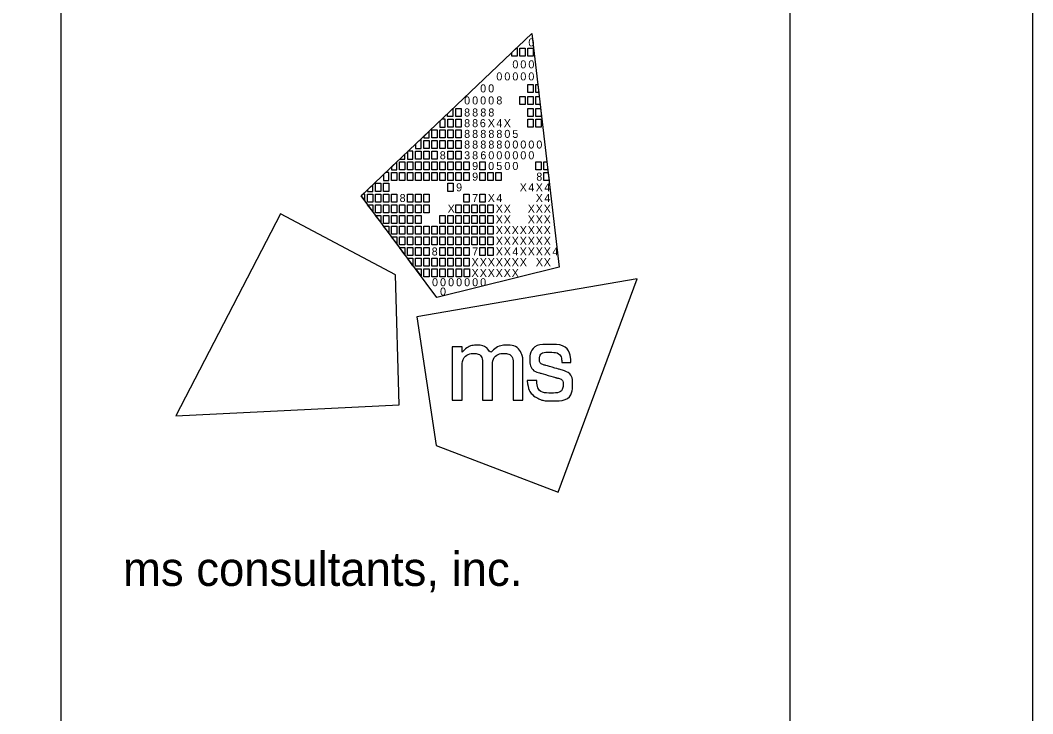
# Model space of a CAD drawing. Extents: x 0 to 34, y 0 to 22.
# Drawn here: x 31.916 to 34, y 2.686 to 4.114 of the extents above; entities that cross this region are included whole.
import ezdxf

# ---------------------------------------------------------------- set-up
doc = ezdxf.new("R2010")
doc.units = 0
for name, color, linetype in [('SH_Border', 7, 'Continuous'), ('SH_Cut_Line', 7, 'Continuous'), ('SH_Data', 7, 'Continuous')]:
    doc.layers.add(name, color=color, linetype=linetype)

msp = doc.modelspace()

# ---------------------------------------------------------------- linework, layer by layer
at = {"layer": 'SH_Border'}
msp.add_line((32, 0.5), (32, 21.5), dxfattribs=at)
msp.add_lwpolyline([(1.5, 21.5), (33.5, 21.5), (33.5, 0.5), (1.5, 0.5)], close=True, dxfattribs=at)
at = {"layer": 'SH_Cut_Line'}
msp.add_lwpolyline([(0, 0), (34, 0), (34, 22), (0, 22)], close=True, dxfattribs=at)
at = {"layer": 'SH_Data'}
for p, q in [((32.6175, 3.7519), (32.9688, 4.0861)), ((32.9688, 4.0861), (32.9688, 4.0861)), ((32.9688, 4.0861), (33.0253, 3.6052)), ((32.773, 3.543), (32.6175, 3.7519)), ((33.0253, 3.6052), (32.773, 3.543)), ((32.75, 3.5), (32.75, 3.5))]:
    msp.add_line(p, q, dxfattribs=at)
for points in [[(32.9279, 4.0472), (32.9369, 4.0558), (32.9389, 4.0558), (32.9389, 4.0393), (32.9279, 4.0393)], [(32.9444, 4.0558), (32.9554, 4.0558), (32.9554, 4.0393), (32.9444, 4.0393)], [(32.9609, 4.0558), (32.9719, 4.0558), (32.9719, 4.0393), (32.9609, 4.0393)], [(32.9606, 3.9815), (32.9716, 3.9815), (32.9716, 3.965), (32.9606, 3.965)], [(32.9771, 3.9815), (32.9811, 3.9815), (32.983, 3.965), (32.9771, 3.965)], [(32.9441, 3.9567), (32.9551, 3.9567), (32.9551, 3.9402), (32.9441, 3.9402)], [(32.9606, 3.9567), (32.9716, 3.9567), (32.9716, 3.9402), (32.9606, 3.9402)], [(32.9771, 3.9567), (32.984, 3.9567), (32.9859, 3.9402), (32.9771, 3.9402)], [(32.7953, 3.9211), (32.8064, 3.9316), (32.8064, 3.9154), (32.7953, 3.9154)], [(32.8123, 3.9319), (32.8233, 3.9319), (32.8233, 3.9154), (32.8123, 3.9154)], [(32.9606, 3.9319), (32.9716, 3.9319), (32.9716, 3.9154), (32.9606, 3.9154)], [(32.9771, 3.9319), (32.9869, 3.9319), (32.9881, 3.9218), (32.9881, 3.9154), (32.9771, 3.9154)], [(32.7958, 3.9099), (32.8068, 3.9099), (32.8068, 3.8934), (32.7958, 3.8934)], [(32.8123, 3.9099), (32.8233, 3.9099), (32.8233, 3.8934), (32.8123, 3.8934)], [(32.9606, 3.9099), (32.9716, 3.9099), (32.9716, 3.8934), (32.9606, 3.8934)], [(32.9771, 3.9099), (32.9881, 3.9099), (32.9881, 3.8934), (32.9771, 3.8934)], [(32.7627, 3.8879), (32.7737, 3.8879), (32.7737, 3.8714), (32.7627, 3.8714)], [(32.7793, 3.8879), (32.7903, 3.8879), (32.7903, 3.8714), (32.7793, 3.8714)], [(32.7958, 3.8879), (32.8068, 3.8879), (32.8068, 3.8714), (32.7958, 3.8714)], [(32.8123, 3.8879), (32.8233, 3.8879), (32.8233, 3.8714), (32.8123, 3.8714)], [(32.7462, 3.8659), (32.7572, 3.8659), (32.7572, 3.8494), (32.7462, 3.8494)], [(32.7627, 3.8659), (32.7737, 3.8659), (32.7737, 3.8494), (32.7627, 3.8494)], [(32.7793, 3.8659), (32.7903, 3.8659), (32.7903, 3.8494), (32.7793, 3.8494)], [(32.7958, 3.8659), (32.8068, 3.8659), (32.8068, 3.8494), (32.7958, 3.8494)], [(32.8123, 3.8659), (32.8233, 3.8659), (32.8233, 3.8494), (32.8123, 3.8494)], [(32.7297, 3.8439), (32.7407, 3.8439), (32.7407, 3.8273), (32.7297, 3.8273)], [(32.7462, 3.8439), (32.7572, 3.8439), (32.7572, 3.8273), (32.7462, 3.8273)], [(32.7627, 3.8439), (32.7737, 3.8439), (32.7737, 3.8273), (32.7627, 3.8273)], [(32.7958, 3.8439), (32.8068, 3.8439), (32.8068, 3.8273), (32.7958, 3.8273)], [(32.8123, 3.8439), (32.8233, 3.8439), (32.8233, 3.8273), (32.8123, 3.8273)], [(32.6967, 3.8218), (32.7077, 3.8218), (32.7077, 3.8053), (32.6967, 3.8053)], [(32.7132, 3.8218), (32.7242, 3.8218), (32.7242, 3.8053), (32.7132, 3.8053)], [(32.7297, 3.8218), (32.7407, 3.8218), (32.7407, 3.8053), (32.7297, 3.8053)], [(32.7462, 3.8218), (32.7572, 3.8218), (32.7572, 3.8053), (32.7462, 3.8053)], [(32.7627, 3.8218), (32.7737, 3.8218), (32.7737, 3.8053), (32.7627, 3.8053)], [(32.7793, 3.8218), (32.7903, 3.8218), (32.7903, 3.8053), (32.7793, 3.8053)], [(32.7958, 3.8218), (32.8068, 3.8218), (32.8068, 3.8053), (32.7958, 3.8053)], [(32.8123, 3.8218), (32.8233, 3.8218), (32.8233, 3.8053), (32.8123, 3.8053)], [(32.8288, 3.8218), (32.8398, 3.8218), (32.8398, 3.8053), (32.8288, 3.8053)], [(32.8618, 3.8218), (32.8728, 3.8218), (32.8728, 3.8053), (32.8618, 3.8053)], [(32.9771, 3.8218), (32.9881, 3.8218), (32.9881, 3.8053), (32.9771, 3.8053)], [(32.9935, 3.8218), (32.9998, 3.8218), (33.0018, 3.8053), (32.9935, 3.8053)], [(32.6802, 3.7998), (32.6912, 3.7998), (32.6912, 3.7833), (32.6802, 3.7833)], [(32.6967, 3.7998), (32.7077, 3.7998), (32.7077, 3.7833), (32.6967, 3.7833)], [(32.7132, 3.7998), (32.7242, 3.7998), (32.7242, 3.7833), (32.7132, 3.7833)], [(32.7297, 3.7998), (32.7407, 3.7998), (32.7407, 3.7833), (32.7297, 3.7833)], [(32.7462, 3.7998), (32.7572, 3.7998), (32.7572, 3.7833), (32.7462, 3.7833)], [(32.7627, 3.7998), (32.7737, 3.7998), (32.7737, 3.7833), (32.7627, 3.7833)], [(32.7793, 3.7998), (32.7903, 3.7998), (32.7903, 3.7833), (32.7793, 3.7833)], [(32.7958, 3.7998), (32.8068, 3.7998), (32.8068, 3.7833), (32.7958, 3.7833)], [(32.8123, 3.7998), (32.8233, 3.7998), (32.8233, 3.7833), (32.8123, 3.7833)], [(32.8288, 3.7998), (32.8398, 3.7998), (32.8398, 3.7833), (32.8288, 3.7833)], [(32.8618, 3.7998), (32.8728, 3.7998), (32.8728, 3.7833), (32.8618, 3.7833)], [(32.8783, 3.7998), (32.8893, 3.7998), (32.8893, 3.7833), (32.8783, 3.7833)], [(32.8947, 3.7998), (32.9057, 3.7998), (32.9057, 3.7833), (32.8947, 3.7833)], [(32.9935, 3.7998), (33.0024, 3.7998), (33.0044, 3.7833), (32.9935, 3.7833)], [(32.6471, 3.7778), (32.6581, 3.7778), (32.6581, 3.7613), (32.6471, 3.7613)], [(32.6637, 3.7778), (32.6747, 3.7778), (32.6747, 3.7613), (32.6637, 3.7613)], [(32.7958, 3.7778), (32.8068, 3.7778), (32.8068, 3.7613), (32.7958, 3.7613)], [(32.6306, 3.7558), (32.6416, 3.7558), (32.6416, 3.7393), (32.6306, 3.7393)], [(32.6471, 3.7558), (32.6581, 3.7558), (32.6581, 3.7393), (32.6471, 3.7393)], [(32.6637, 3.7558), (32.6747, 3.7558), (32.6747, 3.7393), (32.6637, 3.7393)], [(32.6802, 3.7558), (32.6912, 3.7558), (32.6912, 3.7393), (32.6802, 3.7393)], [(32.7132, 3.7558), (32.7242, 3.7558), (32.7242, 3.7393), (32.7132, 3.7393)], [(32.7297, 3.7558), (32.7407, 3.7558), (32.7407, 3.7393), (32.7297, 3.7393)], [(32.7462, 3.7558), (32.7572, 3.7558), (32.7572, 3.7393), (32.7462, 3.7393)], [(32.8288, 3.7558), (32.8398, 3.7558), (32.8398, 3.7393), (32.8288, 3.7393)], [(32.8618, 3.7558), (32.8728, 3.7558), (32.8728, 3.7393), (32.8618, 3.7393)], [(32.6306, 3.7338), (32.6416, 3.7338), (32.6416, 3.72)], [(32.6471, 3.7338), (32.6581, 3.7338), (32.6581, 3.7173), (32.6471, 3.7173)], [(32.6637, 3.7338), (32.6747, 3.7338), (32.6747, 3.7173), (32.6637, 3.7173)], [(32.6802, 3.7338), (32.6912, 3.7338), (32.6912, 3.7173), (32.6802, 3.7173)], [(32.6967, 3.7338), (32.7077, 3.7338), (32.7077, 3.7173), (32.6967, 3.7173)], [(32.7132, 3.7338), (32.7242, 3.7338), (32.7242, 3.7173), (32.7132, 3.7173)], [(32.7297, 3.7338), (32.7407, 3.7338), (32.7407, 3.7173), (32.7297, 3.7173)], [(32.7462, 3.7338), (32.7572, 3.7338), (32.7572, 3.7173), (32.7462, 3.7173)], [(32.8123, 3.7338), (32.8233, 3.7338), (32.8233, 3.7173), (32.8123, 3.7173)], [(32.8288, 3.7338), (32.8398, 3.7338), (32.8398, 3.7173), (32.8288, 3.7173)], [(32.8453, 3.7338), (32.8563, 3.7338), (32.8563, 3.7173), (32.8453, 3.7173)], [(32.8618, 3.7338), (32.8728, 3.7338), (32.8728, 3.7173), (32.8618, 3.7173)], [(32.8783, 3.7338), (32.8893, 3.7338), (32.8893, 3.7173), (32.8783, 3.7173)], [(32.6471, 3.7117), (32.6581, 3.7117), (32.6581, 3.698)], [(32.6637, 3.7117), (32.6747, 3.7117), (32.6747, 3.6952), (32.6637, 3.6952)], [(32.6802, 3.7117), (32.6912, 3.7117), (32.6912, 3.6952), (32.6802, 3.6952)], [(32.6967, 3.7117), (32.7077, 3.7117), (32.7077, 3.6952), (32.6967, 3.6952)], [(32.7132, 3.7117), (32.7242, 3.7117), (32.7242, 3.6952), (32.7132, 3.6952)], [(32.7297, 3.7117), (32.7407, 3.7117), (32.7407, 3.6952), (32.7297, 3.6952)], [(32.7793, 3.7117), (32.7903, 3.7117), (32.7903, 3.6952), (32.7793, 3.6952)], [(32.7958, 3.7117), (32.8068, 3.7117), (32.8068, 3.6952), (32.7958, 3.6952)], [(32.8123, 3.7117), (32.8233, 3.7117), (32.8233, 3.6952), (32.8123, 3.6952)], [(32.8288, 3.7117), (32.8398, 3.7117), (32.8398, 3.6952), (32.8288, 3.6952)], [(32.8453, 3.7117), (32.8563, 3.7117), (32.8563, 3.6952), (32.8453, 3.6952)], [(32.8618, 3.7117), (32.8728, 3.7117), (32.8728, 3.6952), (32.8618, 3.6952)], [(32.8783, 3.7117), (32.8893, 3.7117), (32.8893, 3.6952), (32.8783, 3.6952)], [(32.6637, 3.6897), (32.6747, 3.6897), (32.6747, 3.676)], [(32.6747, 3.6897), (32.6747, 3.6897), (32.6747, 3.6897)], [(32.6802, 3.6897), (32.6912, 3.6897), (32.6912, 3.6732), (32.6802, 3.6732)], [(32.6967, 3.6897), (32.7077, 3.6897), (32.7077, 3.6732), (32.6967, 3.6732)], [(32.7132, 3.6897), (32.7242, 3.6897), (32.7242, 3.6732), (32.7132, 3.6732)], [(32.7297, 3.6897), (32.7407, 3.6897), (32.7407, 3.6732), (32.7297, 3.6732)], [(32.7462, 3.6897), (32.7572, 3.6897), (32.7572, 3.6732), (32.7462, 3.6732)], [(32.7627, 3.6897), (32.7737, 3.6897), (32.7737, 3.6732), (32.7627, 3.6732)], [(32.7793, 3.6897), (32.7903, 3.6897), (32.7903, 3.6732), (32.7793, 3.6732)], [(32.7958, 3.6897), (32.8068, 3.6897), (32.8068, 3.6732), (32.7958, 3.6732)], [(32.8123, 3.6897), (32.8233, 3.6897), (32.8233, 3.6732), (32.8123, 3.6732)], [(32.8288, 3.6897), (32.8398, 3.6897), (32.8398, 3.6732), (32.8288, 3.6732)], [(32.8453, 3.6897), (32.8563, 3.6897), (32.8563, 3.6732), (32.8453, 3.6732)], [(32.8618, 3.6897), (32.8728, 3.6897), (32.8728, 3.6732), (32.8618, 3.6732)], [(32.8783, 3.6897), (32.8893, 3.6897), (32.8893, 3.6732), (32.8783, 3.6732)], [(32.6802, 3.6677), (32.6912, 3.6677), (32.6912, 3.654)], [(32.6967, 3.6677), (32.7077, 3.6677), (32.7077, 3.6512), (32.6967, 3.6512)], [(32.7132, 3.6677), (32.7242, 3.6677), (32.7242, 3.6512), (32.7132, 3.6512)], [(32.7297, 3.6677), (32.7407, 3.6677), (32.7407, 3.6512), (32.7297, 3.6512)], [(32.7462, 3.6677), (32.7572, 3.6677), (32.7572, 3.6512), (32.7462, 3.6512)], [(32.7627, 3.6677), (32.7737, 3.6677), (32.7737, 3.6512), (32.7627, 3.6512)], [(32.7793, 3.6677), (32.7903, 3.6677), (32.7903, 3.6512), (32.7793, 3.6512)], [(32.7958, 3.6677), (32.8068, 3.6677), (32.8068, 3.6512), (32.7958, 3.6512)], [(32.8123, 3.6677), (32.8233, 3.6677), (32.8233, 3.6512), (32.8123, 3.6512)], [(32.8288, 3.6677), (32.8398, 3.6677), (32.8398, 3.6512), (32.8288, 3.6512)], [(32.8453, 3.6677), (32.8563, 3.6677), (32.8563, 3.6512), (32.8453, 3.6512)], [(32.8618, 3.6677), (32.8728, 3.6677), (32.8728, 3.6512), (32.8618, 3.6512)], [(32.8783, 3.6677), (32.8893, 3.6677), (32.8893, 3.6512), (32.8783, 3.6512)], [(32.7077, 3.6305), (32.6965, 3.6457), (32.7077, 3.6457)], [(32.7132, 3.6457), (32.7242, 3.6457), (32.7242, 3.6292), (32.7132, 3.6292)], [(32.7297, 3.6457), (32.7407, 3.6457), (32.7407, 3.6292), (32.7297, 3.6292)], [(32.7462, 3.6457), (32.7572, 3.6457), (32.7572, 3.6292), (32.7462, 3.6292)], [(32.7793, 3.6457), (32.7903, 3.6457), (32.7903, 3.6292), (32.7793, 3.6292)], [(32.7958, 3.6457), (32.8068, 3.6457), (32.8068, 3.6292), (32.7958, 3.6292)], [(32.8123, 3.6457), (32.8233, 3.6457), (32.8233, 3.6292), (32.8123, 3.6292)], [(32.8288, 3.6457), (32.8398, 3.6457), (32.8398, 3.6292), (32.8288, 3.6292)], [(32.8618, 3.6457), (32.8728, 3.6457), (32.8728, 3.6292), (32.8618, 3.6292)], [(32.8783, 3.6457), (32.8893, 3.6457), (32.8893, 3.6292), (32.8783, 3.6292)], [(32.724, 3.6082), (32.7132, 3.6237), (32.7242, 3.6237)], [(32.7297, 3.6237), (32.7407, 3.6237), (32.7407, 3.6072), (32.7297, 3.6072)], [(32.7462, 3.6237), (32.7572, 3.6237), (32.7572, 3.6072), (32.7462, 3.6072)], [(32.7627, 3.6237), (32.7737, 3.6237), (32.7737, 3.6072), (32.7627, 3.6072)], [(32.7793, 3.6237), (32.7903, 3.6237), (32.7903, 3.6072), (32.7793, 3.6072)], [(32.7958, 3.6237), (32.8068, 3.6237), (32.8068, 3.6072), (32.7958, 3.6072)], [(32.8123, 3.6237), (32.8233, 3.6237), (32.8233, 3.6072), (32.8123, 3.6072)], [(32.8288, 3.6237), (32.8398, 3.6237), (32.8398, 3.6072), (32.8288, 3.6072)], [(32.7302, 3.6017), (32.7407, 3.6017), (32.7408, 3.5875)], [(32.7463, 3.6017), (32.7573, 3.6017), (32.7573, 3.5852), (32.7463, 3.5852)], [(32.763, 3.6017), (32.774, 3.6017), (32.774, 3.5852), (32.763, 3.5852)], [(32.7794, 3.6017), (32.7904, 3.6017), (32.7904, 3.5852), (32.7794, 3.5852)], [(32.796, 3.6017), (32.807, 3.6017), (32.807, 3.5852), (32.796, 3.5852)], [(32.8129, 3.6017), (32.8239, 3.6017), (32.8239, 3.5851), (32.8129, 3.5851)], [(32.8296, 3.6017), (32.8406, 3.6017), (32.8406, 3.5851), (32.8296, 3.5851)]]:
    msp.add_lwpolyline(points, close=True, dxfattribs=at)
for points in [[(32.7903, 3.9099), (32.7836, 3.9099), (32.7793, 3.9058), (32.7793, 3.8934), (32.7903, 3.8934), (32.7903, 3.9099)], [(32.7572, 3.8849), (32.7462, 3.8744), (32.7462, 3.8714), (32.7572, 3.8714), (32.7572, 3.8849)], [(32.7407, 3.8691), (32.7297, 3.8587), (32.7297, 3.8494), (32.7407, 3.8494), (32.7407, 3.8691)], [(32.7077, 3.8377), (32.6968, 3.8273), (32.7077, 3.8273), (32.7077, 3.8377)], [(32.7242, 3.8439), (32.7141, 3.8439), (32.7132, 3.843), (32.7132, 3.8273), (32.7242, 3.8273), (32.7242, 3.8439)], [(32.6912, 3.822), (32.6802, 3.8115), (32.6802, 3.8053), (32.6912, 3.8053), (32.6912, 3.822)], [(32.6747, 3.7998), (32.6679, 3.7998), (32.6637, 3.7958), (32.6637, 3.7833), (32.6747, 3.7833), (32.6747, 3.7998)], [(32.6416, 3.7749), (32.6306, 3.7644), (32.6306, 3.7613), (32.6416, 3.7613), (32.6416, 3.7749)], [(32.6251, 3.7558), (32.6216, 3.7558), (32.6175, 3.7519), (32.6251, 3.7417), (32.6251, 3.7558)], [(32.4512, 3.7149), (32.2359, 3.2988), (32.6956, 3.3215), (32.6884, 3.5892), (32.4512, 3.7149)], [(33.0229, 3.1422), (33.1859, 3.5814), (32.7324, 3.5029), (32.7722, 3.2381), (33.0229, 3.1422)]]:
    msp.add_lwpolyline(points, dxfattribs=at)
for points in [[(32.8048, 3.3315), (32.8048, 3.3315), (32.8048, 3.4409), (32.8048, 3.4409), (32.8048, 3.4409), (32.8255, 3.4409), (32.8255, 3.4409), (32.8255, 3.4409), (32.8255, 3.4297), (32.8255, 3.4297), (32.8346, 3.4399), (32.8457, 3.4445), (32.8555, 3.4445), (32.8688, 3.4445), (32.8791, 3.4372), (32.8837, 3.4266), (32.8915, 3.4381), (32.905, 3.4446), (32.9166, 3.4446), (32.9325, 3.4446), (32.9451, 3.435), (32.9494, 3.4213), (32.9494, 3.4212), (32.9494, 3.4212), (32.9494, 3.4212), (32.9501, 3.419), (32.9506, 3.4172), (32.9506, 3.4071), (32.9506, 3.4071), (32.9506, 3.3314), (32.9506, 3.3314), (32.9506, 3.3314), (32.9303, 3.3314), (32.9303, 3.3314), (32.9303, 3.3314), (32.9303, 3.4048), (32.9303, 3.4048), (32.9303, 3.4201), (32.9219, 3.4274), (32.911, 3.4274), (32.8995, 3.4274), (32.8879, 3.4171), (32.8879, 3.4001), (32.8879, 3.4001), (32.8879, 3.3315), (32.8879, 3.3315), (32.8879, 3.3315), (32.8674, 3.3315), (32.8674, 3.3315), (32.8674, 3.3315), (32.8674, 3.4059), (32.8674, 3.4059), (32.8674, 3.4203), (32.8588, 3.4274), (32.8496, 3.4274), (32.8384, 3.4274), (32.8254, 3.417), (32.8254, 3.3962), (32.8254, 3.3962), (32.8254, 3.3315), (32.8254, 3.3315), (32.8254, 3.3315), (32.8048, 3.3315), (32.8048, 3.3315)], [(32.9595, 3.3709), (32.9595, 3.3709), (32.9595, 3.3717), (32.9595, 3.3717), (32.9595, 3.3717), (32.9603, 3.3717), (32.9603, 3.3717), (32.9603, 3.3717), (32.9783, 3.3717), (32.9783, 3.3717), (32.9783, 3.3717), (32.9789, 3.3717), (32.9789, 3.3717), (32.9789, 3.3717), (32.979, 3.371), (32.979, 3.371), (32.9803, 3.3554), (32.9887, 3.346), (33.009, 3.346), (33.0273, 3.346), (33.0333, 3.3554), (33.0333, 3.3631), (33.0333, 3.3732), (33.0256, 3.3758), (33.0175, 3.378), (33.0175, 3.378), (32.987, 3.3867), (32.987, 3.3867), (32.972, 3.3909), (32.9648, 3.4019), (32.9648, 3.4142), (32.9648, 3.4303), (32.9768, 3.4462), (33.0052, 3.4462), (33.0348, 3.4462), (33.0489, 3.4285), (33.0489, 3.4095), (33.0489, 3.4095), (33.0489, 3.4087), (33.0489, 3.4087), (33.0489, 3.4087), (33.0482, 3.4087), (33.0482, 3.4087), (33.0482, 3.4087), (33.0312, 3.4087), (33.0312, 3.4087), (33.0312, 3.4087), (33.0305, 3.4087), (33.0305, 3.4087), (33.0305, 3.4087), (33.0305, 3.4094), (33.0305, 3.4094), (33.0301, 3.4208), (33.0226, 3.43), (33.0056, 3.43), (32.9891, 3.43), (32.9843, 3.4218), (32.9843, 3.4157), (32.9843, 3.4108), (32.9869, 3.4059), (32.9959, 3.4033), (32.9959, 3.4033), (33.0255, 3.3948), (33.0255, 3.3948), (33.0462, 3.3889), (33.0527, 3.3777), (33.0527, 3.3639), (33.0527, 3.3462), (33.041, 3.3298), (33.0087, 3.3298), (32.9952, 3.3298), (32.9877, 3.3321), (32.9823, 3.3348), (32.969, 3.3414), (32.9609, 3.3536), (32.9595, 3.3709)]]:
    msp.add_open_spline(points, degree=3, dxfattribs=at)

# ---------------------------------------------------------------- texts
for s, height, p in [('0', 0.0165, (32.9617, 4.0597)), ('0', 0.0165, (32.9288, 4.0145)), ('0', 0.0165, (32.9452, 4.0145)), ('0', 0.0165, (32.9617, 4.0145)), ('0', 0.0165, (32.8958, 3.9897)), ('0', 0.0165, (32.9123, 3.9897)), ('0', 0.0165, (32.9288, 3.9897)), ('0', 0.0165, (32.9452, 3.9897)), ('0', 0.0165, (32.9617, 3.9897)), ('0', 0.0165, (32.8625, 3.965)), ('0', 0.0165, (32.879, 3.965)), ('0', 0.0165, (32.8295, 3.9402)), ('0', 0.0165, (32.846, 3.9402)), ('0', 0.0165, (32.8625, 3.9402)), ('0', 0.0165, (32.879, 3.9402)), ('8', 0.0165, (32.8958, 3.9402)), ('8', 0.0165, (32.8295, 3.9154)), ('8', 0.0165, (32.846, 3.9154)), ('8', 0.0165, (32.8628, 3.9154)), ('8', 0.0165, (32.8793, 3.9154)), ('8', 0.0165, (32.8295, 3.8934)), ('8', 0.0165, (32.846, 3.8934)), ('6', 0.0165, (32.8618, 3.8934)), ('X', 0.0165, (32.8781, 3.8934)), ('4', 0.0165, (32.8958, 3.8934)), ('X', 0.0165, (32.911, 3.8934)), ('8', 0.0165, (32.8295, 3.8713)), ('8', 0.0165, (32.846, 3.8713)), ('8', 0.0165, (32.8628, 3.8713)), ('8', 0.0165, (32.8794, 3.8713)), ('8', 0.0165, (32.8958, 3.8713)), ('0', 0.0165, (32.9123, 3.8713)), ('5', 0.0165, (32.9287, 3.8713)), ('8', 0.0165, (32.8295, 3.8494)), ('8', 0.0165, (32.846, 3.8494)), ('8', 0.0165, (32.8628, 3.8494)), ('8', 0.0165, (32.8794, 3.8494)), ('8', 0.0165, (32.8958, 3.8494)), ('0', 0.0165, (32.9123, 3.8494)), ('0', 0.0165, (32.9288, 3.8494)), ('0', 0.0165, (32.9452, 3.8494)), ('0', 0.0165, (32.9617, 3.8494)), ('0', 0.0165, (32.9782, 3.8494)), ('8', 0.0165, (32.7793, 3.8273)), ('3', 0.0165, (32.8295, 3.8273)), ('8', 0.0165, (32.846, 3.8273)), ('6', 0.0165, (32.8629, 3.8273)), ('0', 0.0165, (32.8793, 3.8273)), ('0', 0.0165, (32.8958, 3.8273)), ('0', 0.0165, (32.9123, 3.8273)), ('0', 0.0165, (32.9288, 3.8273)), ('0', 0.0165, (32.9452, 3.8273)), ('0', 0.0165, (32.9617, 3.8273)), ('9', 0.0165, (32.846, 3.8053)), ('0', 0.0165, (32.879, 3.8053)), ('5', 0.0165, (32.8957, 3.8053)), ('0', 0.0165, (32.9123, 3.8053)), ('0', 0.0165, (32.9288, 3.8053)), ('9', 0.0165, (32.846, 3.7833)), ('8', 0.0165, (32.9781, 3.7833)), ('9', 0.0165, (32.813, 3.7613)), ('X', 0.0165, (32.9439, 3.7613)), ('4', 0.0165, (32.9617, 3.7613)), ('X', 0.0165, (32.9769, 3.7613)), ('4', 0.0165, (32.9946, 3.7613)), ('8', 0.0165, (32.6967, 3.7393)), ('7', 0.0165, (32.846, 3.7393)), ('X', 0.0165, (32.8781, 3.7393)), ('4', 0.0165, (32.8958, 3.7393)), ('X', 0.0165, (32.9769, 3.7393)), ('4', 0.0165, (32.9946, 3.7393)), ('X', 0.0165, (32.7955, 3.7173)), ('X', 0.0165, (32.8945, 3.7173)), ('X', 0.0165, (32.911, 3.7173)), ('X', 0.0165, (32.9604, 3.7173)), ('X', 0.0165, (32.9769, 3.7173)), ('X', 0.0165, (32.9933, 3.7173)), ('X', 0.0165, (32.8945, 3.6952)), ('X', 0.0165, (32.911, 3.6952)), ('X', 0.0165, (32.9604, 3.6952)), ('X', 0.0165, (32.9769, 3.6952)), ('X', 0.0165, (32.9933, 3.6952)), ('X', 0.0165, (32.8945, 3.6732)), ('X', 0.0165, (32.911, 3.6732)), ('X', 0.0165, (32.9274, 3.6732)), ('X', 0.0165, (32.9439, 3.6732)), ('X', 0.0165, (32.9604, 3.6732)), ('X', 0.0165, (32.9769, 3.6732)), ('X', 0.0165, (32.9933, 3.6732)), ('X', 0.0165, (32.8945, 3.6512)), ('X', 0.0165, (32.911, 3.6512)), ('X', 0.0165, (32.9274, 3.6512)), ('X', 0.0165, (32.9439, 3.6512)), ('X', 0.0165, (32.9604, 3.6512)), ('X', 0.0165, (32.9769, 3.6512)), ('X', 0.0165, (32.9933, 3.6512)), ('8', 0.0165, (32.7627, 3.6292)), ('7', 0.0165, (32.846, 3.6292)), ('X', 0.0165, (32.8945, 3.6292)), ('X', 0.0165, (32.911, 3.6292)), ('4', 0.0165, (32.9288, 3.6292)), ('X', 0.0165, (32.9439, 3.6292)), ('X', 0.0165, (32.9604, 3.6292)), ('X', 0.0165, (32.9769, 3.6292)), ('X', 0.0165, (32.9933, 3.6292)), ('4', 0.0165, (33.0111, 3.6292)), ('X', 0.0165, (32.8447, 3.6072)), ('X', 0.0165, (32.8616, 3.6072)), ('X', 0.0165, (32.878, 3.6072)), ('X', 0.0165, (32.8945, 3.6072)), ('X', 0.0165, (32.911, 3.6072)), ('X', 0.0165, (32.9274, 3.6072)), ('X', 0.0165, (32.9439, 3.6072)), ('X', 0.0165, (32.9771, 3.6072)), ('X', 0.0165, (32.9933, 3.6072)), ('X', 0.0165, (32.8447, 3.5851)), ('X', 0.0165, (32.8616, 3.5851)), ('X', 0.0165, (32.878, 3.5851)), ('X', 0.0165, (32.8945, 3.5851)), ('X', 0.0165, (32.911, 3.5851)), ('X', 0.0165, (32.9274, 3.5851)), ('0', 0.0165, (32.7634, 3.5659)), ('0', 0.0165, (32.7799, 3.5659)), ('0', 0.0165, (32.7965, 3.5659)), ('0', 0.0165, (32.813, 3.5659)), ('0', 0.0165, (32.8295, 3.5659)), ('0', 0.0165, (32.846, 3.5659)), ('0', 0.0165, (32.8625, 3.5659)), ('0', 0.0165, (32.7799, 3.5467)), ('ms consultants, inc.', 0.07, (32.1273, 2.9489))]:
    msp.add_text(s, height=height, rotation=360, dxfattribs=at).set_placement(p)

doc.saveas('drawing.dxf')
